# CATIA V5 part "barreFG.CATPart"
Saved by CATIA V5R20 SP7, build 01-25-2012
Part number: barreFG
Publications: "pivot_FG_EF", "pivot_FG_base", "Plan_Ref"
Bounding box of the stored display mesh (mm): x 7 to 19, y -15 to 31.109, z -14.996 to 294.533
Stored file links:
  G:\IAO\apres\barreFG.CATPart
  G:\IAO\apres\psedsuay.CATProduct
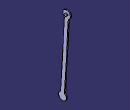
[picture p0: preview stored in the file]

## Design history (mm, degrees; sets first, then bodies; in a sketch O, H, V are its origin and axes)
External parameters (linked from other documents)
  External.Longueur_AB = 100 mm
  External.Epaisseur = 4 mm
  External.Largeur = 15 mm
  External.Diametre = 30 mm
  External.Diametre_pivot = 10 mm
Set1
  Point1 "Point_F": linked copy from another document
  Point2 "Point_G": linked copy from another document
  Plane1 "Plan_Ref": linked copy from another document
Set2 "skelette"
  Line1 "Barre_FG": type PtPt, FirstPoint Point1, SecondPoint Point2
  Line2 "pivot_FG_EF": type Normal, RefPoint Point1, RefSkin Plane1, Start -20, End 20
  Line3 "pivot_FG_base": type Normal, RefPoint Point2, RefSkin Plane1, Start -20, End 20
Set3 "piece"
  Plane2: type OffsetPt, RefPlane yz-plane, RefPoint Point2
  Plane3: type Offset, RefPlane Plane2, Offset 11 {= 0.15*External.Longueur_AB -External.Epaisseur}
  Sketch1 on Plane3, origin (11, 0, 0), H (0, 1, 0), V (0, 0, 1)
    arc A1 centre (16.1097, 279.5362) radius 15 from (22.8499, 266.1358) to (7.8748, 266.9988) ccw
    arc A2 centre (0, 0) radius 15 from (-6.7402, 13.4004) to (8.235, 12.5374) ccw
    construction line L1 (16.1097, 279.5362) -> (0, 0)
    line L2 (-6.7402, 13.4004) -> (7.8748, 266.9988)
    line L3 (8.235, 12.5374) -> (22.8499, 266.1358)
    reference projected point E1 (16.1097, 279.5362) from Line2
    reference projected point E2 (0, 0) from Line3
    radius A1 = 15 {= External.Diametre /2}
    radius A2 = 15 {= External.Diametre /2}
    distance L3 L2 = 15 {= External.Largeur}
    parallelism: L2 L1, L3 L1
    symmetry: L3 L2 L1
    concentricity: A1 E1, A2 E2
  Plane4: type Offset, RefPlane Plane3, Offset 4 {= External.Epaisseur}
  Sketch2 on Plane3, origin (11, 0, 0), H (0, 1, 0), V (0, 0, 1)
    circle A1 centre (0, 0) radius 5
    reference projected point E1 (0, 0) from Line3
    radius A1 = 5 {= External.Diametre_pivot /2}
    concentricity: A1 E1
  Sketch3 on Plane4, origin (15, 0, 0), H (0, 1, 0), V (0, 0, 1)
    circle A1 centre (16.1097, 279.5362) radius 5
    reference projected point E1 (16.1097, 279.5362) from Line2
    radius A1 = 5 {= External.Diametre_pivot /2}
    concentricity: A1 E1
Body1 (main body)
  Pad1: profile Sketch1, direction (1, 0, 0), length 4 {= External.Epaisseur}
  Pad2: profile Sketch2, direction (1, 0, 0), length 4 {= External.Epaisseur}, mirrored extent
  Pad3: profile Sketch3, direction (1, 0, 0), length 4 {= External.Epaisseur}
